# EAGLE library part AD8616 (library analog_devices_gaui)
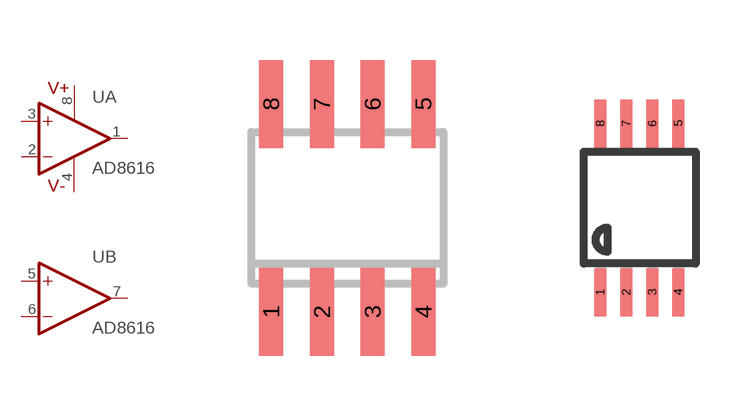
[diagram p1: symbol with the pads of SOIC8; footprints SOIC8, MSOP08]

Designator prefix U; gates B=OP A=OP_PWR

## AD8616AR  [SOIC8]
1  A:OUT  out
2  A:-IN  in
3  A:+IN  in
4  A:V-  pwr
5  B:+IN  in
6  B:-IN  in
7  B:OUT  out
8  A:V+  pwr

## AD8616ARM  [MSOP08]
Pads as for SOIC8

## Footprint SOIC8 (pad centres in mm)
Small Outline IC
smd 0.6 x 2.2: 1 -1.905,-2.6; 2 -0.635,-2.6; 3 0.635,-2.6; 4 1.905,-2.6; 5 1.905,2.6; 6 0.635,2.6; 7 -0.635,2.6; 8 -1.905,2.6

## Footprint MSOP08 (pad centres in mm)
Mini Small Outline Package Grid 0.5mm
smd 0.3 x 1.2: 1 -0.976,-2.113; 2 -0.326,-2.113; 3 0.324,-2.113; 4 0.974,-2.113; 5 0.974,2.112; 6 0.324,2.112; 7 -0.326,2.112; 8 -0.976,2.112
